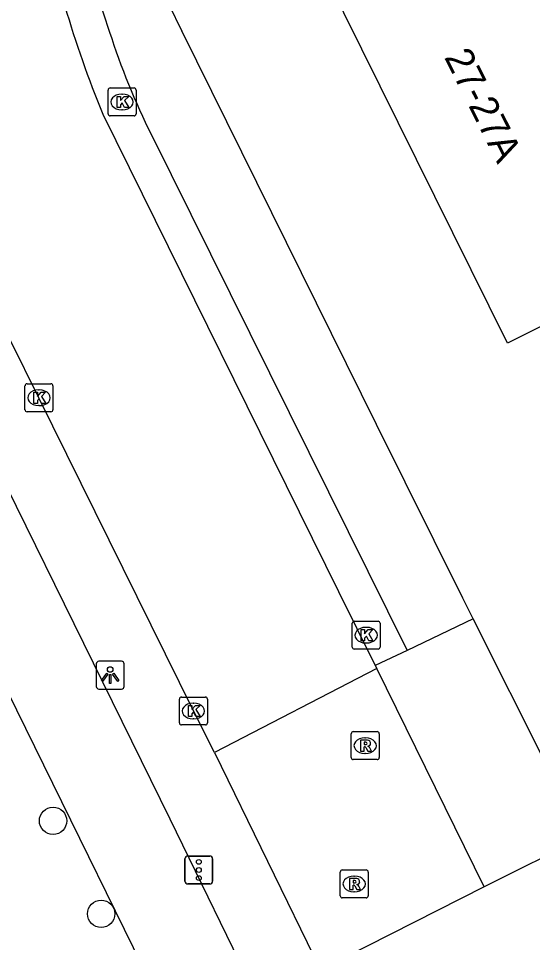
# Model space of a CAD drawing. Extents: x 157692 to 159670, y 381454 to 383289.
# Drawn here: x 158018.97 to 158037.36, y 381561.46 to 381594.48 of the extents above; entities that cross this region are included whole.
import ezdxf

# ---------------------------------------------------------------- set-up
doc = ezdxf.new("R2010")
doc.units = 0
for name, color, linetype in [('IMGEO_Boom', 7, 'Continuous'), ('IMGEO_Fietspad_gesloten', 7, 'Continuous'), ('IMGEO_Groenvoorziening', 7, 'Continuous'), ('IMGEO_Kolk', 7, 'Continuous'), ('IMGEO_Lichtpunt', 7, 'Continuous'), ('IMGEO_Pand', 7, 'Continuous'), ('IMGEO_Pand_nummerreeks', 7, 'Continuous'), ('IMGEO_Rijbaan_lokaal_gesloten', 7, 'Continuous'), ('IMGEO_Rioolput', 7, 'Continuous'), ('IMGEO_Verkeersregelinstallatiepaal', 7, 'Continuous'), ('IMGEO_Voetpad_open', 7, 'Continuous')]:
    doc.layers.add(name, color=color, linetype=linetype)

msp = doc.modelspace()

# ---------------------------------------------------------------- linework, layer by layer
at = {"layer": 'IMGEO_Boom'}
for centre in [(158020.207, 381565.809), (158021.932, 381562.486)]:
    msp.add_circle(centre, 0.489, dxfattribs=at)
at = {"layer": 'IMGEO_Fietspad_gesloten'}
msp.add_lwpolyline([(158039.17, 381565.209), (158035.637, 381563.445)], dxfattribs=at)
at = {"layer": 'IMGEO_Groenvoorziening'}
msp.add_lwpolyline([(158010.552, 381586.734), (158023.394, 381560.624)], dxfattribs=at)
at = {"layer": 'IMGEO_Kolk'}
for p, q in [((158022.177, 381591.074), (158022.177, 381591.926)), ((158022.252, 381592), (158023.104, 381592)), ((158022.665, 381591.78), (158022.69, 381591.78)), ((158023.178, 381591.926), (158023.178, 381591.074)), ((158022.688, 381591.22), (158022.663, 381591.22)), ((158023.104, 381591), (158022.252, 381591)), ((158019.204, 381580.501), (158019.204, 381581.353)), ((158019.279, 381581.427), (158020.131, 381581.427)), ((158019.692, 381581.207), (158019.717, 381581.207)), ((158020.205, 381581.353), (158020.205, 381580.501)), ((158019.715, 381580.647), (158019.69, 381580.647)), ((158020.131, 381580.427), (158019.279, 381580.427)), ((158030.984, 381572.943), (158031.836, 381572.943)), ((158030.909, 381572.017), (158030.909, 381572.869)), ((158031.397, 381572.723), (158031.422, 381572.723)), ((158031.91, 381572.869), (158031.91, 381572.017)), ((158031.42, 381572.163), (158031.395, 381572.163)), ((158031.836, 381571.943), (158030.984, 381571.943)), ((158024.729, 381569.307), (158024.729, 381570.159)), ((158024.804, 381570.233), (158025.656, 381570.233)), ((158025.217, 381570.013), (158025.242, 381570.013)), ((158025.73, 381570.159), (158025.73, 381569.307)), ((158025.24, 381569.453), (158025.215, 381569.453)), ((158025.656, 381569.233), (158024.804, 381569.233))]:
    msp.add_line(p, q, dxfattribs=at)
for points in [[(158022.177, 381591.074), (158022.177, 381591.926)], [(158022.252, 381592), (158023.104, 381592)], [(158023.178, 381591.926), (158023.178, 381591.074)], [(158022.498, 381591.7), (158022.621, 381591.7), (158022.621, 381591.549), (158022.751, 381591.7), (158022.915, 381591.7), (158022.769, 381591.549), (158022.922, 381591.3), (158022.77, 381591.3), (158022.685, 381591.464), (158022.621, 381591.397), (158022.621, 381591.3), (158022.498, 381591.3), (158022.498, 381591.7)], [(158023.104, 381591), (158022.252, 381591)], [(158019.204, 381580.501), (158019.204, 381581.353)], [(158019.279, 381581.427), (158020.131, 381581.427)], [(158020.205, 381581.353), (158020.205, 381580.501)], [(158019.525, 381581.127), (158019.648, 381581.127), (158019.648, 381580.976), (158019.778, 381581.127), (158019.942, 381581.127), (158019.796, 381580.976), (158019.949, 381580.727), (158019.797, 381580.727), (158019.712, 381580.891), (158019.648, 381580.824), (158019.648, 381580.727), (158019.525, 381580.727), (158019.525, 381581.127)], [(158020.131, 381580.427), (158019.279, 381580.427)], [(158030.984, 381572.943), (158031.836, 381572.943)], [(158030.909, 381572.017), (158030.909, 381572.869)], [(158031.23, 381572.643), (158031.353, 381572.643), (158031.353, 381572.492), (158031.483, 381572.643), (158031.647, 381572.643), (158031.501, 381572.492), (158031.654, 381572.243), (158031.502, 381572.243), (158031.417, 381572.407), (158031.353, 381572.34), (158031.353, 381572.243), (158031.23, 381572.243), (158031.23, 381572.643)], [(158031.91, 381572.869), (158031.91, 381572.017)], [(158031.836, 381571.943), (158030.984, 381571.943)], [(158024.729, 381569.307), (158024.729, 381570.159)], [(158024.804, 381570.233), (158025.656, 381570.233)], [(158025.73, 381570.159), (158025.73, 381569.307)], [(158025.05, 381569.933), (158025.173, 381569.933), (158025.173, 381569.782), (158025.303, 381569.933), (158025.467, 381569.933), (158025.321, 381569.782), (158025.474, 381569.533), (158025.322, 381569.533), (158025.237, 381569.697), (158025.173, 381569.63), (158025.173, 381569.533), (158025.05, 381569.533), (158025.05, 381569.933)], [(158025.656, 381569.233), (158024.804, 381569.233)]]:
    msp.add_lwpolyline(points, dxfattribs=at)
for centre, start, end in [((158022.254, 381591.924), 91.552, 178.448), ((158022.254, 381591.924), 91.552, 178.448), ((158023.102, 381591.924), 1.552, 88.448), ((158023.102, 381591.924), 1.552, 88.448), ((158022.254, 381591.076), 181.552, 268.448), ((158022.254, 381591.076), 181.552, 268.448), ((158023.102, 381591.076), 271.552, 358.448), ((158023.102, 381591.076), 271.552, 358.448), ((158019.281, 381581.351), 91.552, 178.448), ((158019.281, 381581.351), 91.552, 178.448), ((158020.129, 381581.351), 1.552, 88.448), ((158020.129, 381581.351), 1.552, 88.448), ((158019.281, 381580.503), 181.552, 268.448), ((158019.281, 381580.503), 181.552, 268.448), ((158020.129, 381580.503), 271.552, 358.448), ((158020.129, 381580.503), 271.552, 358.448), ((158030.986, 381572.867), 91.552, 178.448), ((158030.986, 381572.867), 91.552, 178.448), ((158031.834, 381572.867), 1.552, 88.448), ((158031.834, 381572.867), 1.552, 88.448), ((158030.986, 381572.019), 181.552, 268.448), ((158030.986, 381572.019), 181.552, 268.448), ((158031.834, 381572.019), 271.552, 358.448), ((158031.834, 381572.019), 271.552, 358.448), ((158024.806, 381570.157), 91.552, 178.448), ((158024.806, 381570.157), 91.552, 178.448), ((158025.654, 381570.157), 1.552, 88.448), ((158025.654, 381570.157), 1.552, 88.448), ((158024.806, 381569.309), 181.552, 268.448), ((158024.806, 381569.309), 181.552, 268.448), ((158025.654, 381569.309), 271.552, 358.448), ((158025.654, 381569.309), 271.552, 358.448)]:
    msp.add_arc(centre, 0.0765, start, end, dxfattribs=at)
for centre, major_axis, ratio, start_param, end_param in [((158022.664, 381591.5), (-0.387, 0.002), 0.722429, 4.712389, 7.853982), ((158022.689, 381591.5), (-0.39, 0.002), 0.717154, 1.570796, 4.712389), ((158019.691, 381580.927), (-0.387, 0.002), 0.722429, 4.712389, 7.853982), ((158019.716, 381580.927), (-0.39, 0.002), 0.717154, 1.570796, 4.712389), ((158031.396, 381572.443), (-0.387, 0.002), 0.722429, 4.712389, 7.853982), ((158031.421, 381572.443), (-0.39, 0.002), 0.717154, 1.570796, 4.712389), ((158025.216, 381569.733), (-0.387, 0.002), 0.722429, 4.712389, 7.853982), ((158025.241, 381569.733), (-0.39, 0.002), 0.717154, 1.570796, 4.712389)]:
    msp.add_ellipse(centre, major_axis=major_axis, ratio=ratio, start_param=start_param, end_param=end_param, dxfattribs=at)
at = {"layer": 'IMGEO_Lichtpunt'}
for p, q in [((158021.754, 381571.417), (158021.754, 381570.61)), ((158021.754, 381571.417), (158021.754, 381570.61)), ((158022.656, 381571.512), (158021.848, 381571.512)), ((158022.656, 381571.512), (158021.848, 381571.512)), ((158022.75, 381570.61), (158022.75, 381571.417)), ((158022.75, 381570.61), (158022.75, 381571.417)), ((158021.848, 381570.516), (158022.656, 381570.516)), ((158021.848, 381570.516), (158022.656, 381570.516))]:
    msp.add_line(p, q, dxfattribs=at)
for points in [[(158022.128, 381571.081), (158022.167, 381571.053), (158021.979, 381570.791), (158021.941, 381570.818), (158022.128, 381571.081)], [(158022.23, 381571.033), (158022.277, 381571.033), (158022.277, 381570.711), (158022.23, 381570.711), (158022.23, 381571.033)], [(158022.34, 381571.053), (158022.378, 381571.08), (158022.565, 381570.818), (158022.526, 381570.79), (158022.34, 381571.053)]]:
    msp.add_lwpolyline(points, dxfattribs=at)
msp.add_circle((158022.253, 381571.215), 0.0994, dxfattribs=at)
for centre, start, end in [((158021.848, 381571.417), 90, 180), ((158021.848, 381571.417), 90, 180), ((158022.656, 381571.417), 0, 90), ((158022.656, 381571.417), 0, 90), ((158021.848, 381570.61), 180, 270), ((158021.848, 381570.61), 180, 270), ((158022.656, 381570.61), 270, 0), ((158022.656, 381570.61), 270, 360)]:
    msp.add_arc(centre, 0.0946, start, end, dxfattribs=at)
at = {"layer": 'IMGEO_Pand'}
msp.add_lwpolyline([(158064.672, 381611.766), (158072.18, 381596.56), (158069.93, 381589.9), (158051.49, 381580.76), (158047.667, 381588.475), (158036.468, 381582.877), (158029.955, 381596.02), (158031.319, 381597.702), (158028.607, 381603.083), (158026.871, 381602.244), (158026.64, 381602.71), (158028.252, 381603.508)], dxfattribs=at)
at = {"layer": 'IMGEO_Rijbaan_lokaal_gesloten'}
for points in [[(158021.989, 381591.063), (158030.425, 381574.007), (158031.735, 381571.355)], [(158025.98, 381568.248), (158025.23, 381569.733), (158019.705, 381580.927), (158017.655, 381585.024)], [(158031.735, 381571.355), (158031.795, 381571.252)], [(158031.795, 381571.252), (158025.98, 381568.248)], [(158035.637, 381563.445), (158031.795, 381571.252)], [(158025.98, 381568.248), (158029.771, 381560.479)], [(158035.637, 381563.445), (158029.771, 381560.479)]]:
    msp.add_lwpolyline(points, dxfattribs=at)
msp.add_arc((158058.796, 381606.188), 39.793, 196.4431, 202.3392, dxfattribs=at)
at = {"layer": 'IMGEO_Rioolput'}
for p, q in [((158030.949, 381568.995), (158031.801, 381568.995)), ((158030.874, 381568.069), (158030.874, 381568.921)), ((158031.362, 381568.775), (158031.387, 381568.775)), ((158031.875, 381568.921), (158031.875, 381568.069)), ((158031.801, 381567.995), (158030.949, 381567.995)), ((158031.385, 381568.215), (158031.36, 381568.215)), ((158030.556, 381564.052), (158031.408, 381564.052)), ((158030.481, 381563.126), (158030.481, 381563.978)), ((158030.969, 381563.832), (158030.994, 381563.832)), ((158031.482, 381563.978), (158031.482, 381563.126)), ((158031.408, 381563.052), (158030.556, 381563.052)), ((158030.992, 381563.272), (158030.967, 381563.272))]:
    msp.add_line(p, q, dxfattribs=at)
for points in [[(158030.949, 381568.995), (158031.801, 381568.995)], [(158030.874, 381568.069), (158030.874, 381568.921)], [(158031.463, 381568.693), (158031.211, 381568.695), (158031.211, 381568.295)], [(158031.875, 381568.921), (158031.875, 381568.069)], [(158031.211, 381568.295), (158031.335, 381568.295), (158031.335, 381568.457), (158031.346, 381568.457)], [(158031.389, 381568.614), (158031.335, 381568.614), (158031.335, 381568.533)], [(158031.335, 381568.533), (158031.387, 381568.533)], [(158031.393, 381568.428), (158031.464, 381568.295), (158031.604, 381568.295), (158031.539, 381568.421)], [(158031.801, 381567.995), (158030.949, 381567.995)], [(158030.556, 381564.052), (158031.408, 381564.052)], [(158030.481, 381563.126), (158030.481, 381563.978)], [(158031.07, 381563.75), (158030.818, 381563.752), (158030.818, 381563.352)], [(158031.482, 381563.978), (158031.482, 381563.126)], [(158030.818, 381563.352), (158030.942, 381563.352), (158030.942, 381563.514), (158030.953, 381563.514)], [(158030.996, 381563.671), (158030.942, 381563.671), (158030.942, 381563.59)], [(158030.942, 381563.59), (158030.994, 381563.59)], [(158031, 381563.485), (158031.071, 381563.352), (158031.211, 381563.352), (158031.146, 381563.478)], [(158031.408, 381563.052), (158030.556, 381563.052)]]:
    msp.add_lwpolyline(points, dxfattribs=at)
for centre, radius, start, end in [((158030.951, 381568.919), 0.0765, 91.552, 178.448), ((158030.951, 381568.919), 0.0765, 91.552, 178.448), ((158031.799, 381568.919), 0.0765, 1.552, 88.448), ((158031.799, 381568.919), 0.0765, 1.552, 88.448), ((158031.462, 381568.583), 0.109, 350.3612, 89.416), ((158031.345, 381568.404), 0.0533, 26.0293, 88.6989), ((158031.371, 381568.722), 0.19, 274.7715, 282.9687), ((158031.395, 381568.518), 0.0964, 77.0061, 93.1865), ((158031.409, 381568.575), 0.0378, 276.6634, 79.6772), ((158031.46, 381568.583), 0.112, 277.5842, 350.9817), ((158031.444, 381568.368), 0.108, 29.5134, 73.7905), ((158030.951, 381568.071), 0.0765, 181.552, 268.448), ((158030.951, 381568.071), 0.0765, 181.552, 268.448), ((158031.799, 381568.071), 0.0765, 271.552, 358.448), ((158031.799, 381568.071), 0.0765, 271.552, 358.448), ((158030.558, 381563.976), 0.0765, 91.552, 178.448), ((158030.558, 381563.976), 0.0765, 91.552, 178.448), ((158031.406, 381563.976), 0.0765, 1.552, 88.448), ((158031.406, 381563.976), 0.0765, 1.552, 88.448), ((158031.069, 381563.64), 0.109, 350.3612, 89.416), ((158030.952, 381563.461), 0.0533, 26.0293, 88.6989), ((158030.978, 381563.779), 0.19, 274.7715, 282.9687), ((158031.002, 381563.575), 0.0964, 77.0061, 93.1865), ((158031.016, 381563.632), 0.0378, 276.6634, 79.6772), ((158031.067, 381563.64), 0.112, 277.5842, 350.9817), ((158031.051, 381563.425), 0.108, 29.5134, 73.7905), ((158030.558, 381563.128), 0.0765, 181.552, 268.448), ((158030.558, 381563.128), 0.0765, 181.552, 268.448), ((158031.406, 381563.128), 0.0765, 271.552, 358.448), ((158031.406, 381563.128), 0.0765, 271.552, 358.448)]:
    msp.add_arc(centre, radius, start, end, dxfattribs=at)
for centre, major_axis, ratio, start_param, end_param in [((158031.361, 381568.495), (-0.387, 0.002), 0.722429, 4.712389, 7.853982), ((158031.386, 381568.495), (-0.39, 0.002), 0.717154, 1.570796, 4.712389), ((158030.968, 381563.552), (-0.387, 0.002), 0.722429, 4.712389, 7.853982), ((158030.993, 381563.552), (-0.39, 0.002), 0.717154, 1.570796, 4.712389)]:
    msp.add_ellipse(centre, major_axis=major_axis, ratio=ratio, start_param=start_param, end_param=end_param, dxfattribs=at)
at = {"layer": 'IMGEO_Verkeersregelinstallatiepaal'}
for p, q in [((158024.928, 381563.65), (158024.928, 381564.45)), ((158024.928, 381564.45), (158024.928, 381563.65)), ((158025.028, 381564.55), (158025.818, 381564.55)), ((158025.818, 381564.55), (158025.028, 381564.55)), ((158025.918, 381564.45), (158025.918, 381563.65)), ((158025.918, 381563.65), (158025.918, 381564.45)), ((158025.818, 381563.55), (158025.028, 381563.55)), ((158025.028, 381563.55), (158025.818, 381563.55))]:
    msp.add_line(p, q, dxfattribs=at)
for centre in [(158025.423, 381564.34), (158025.423, 381564.05), (158025.423, 381563.76)]:
    msp.add_circle(centre, 0.085, dxfattribs=at)
for centre, start, end in [((158025.028, 381564.45), 90, 180), ((158025.028, 381564.45), 90, 180), ((158025.818, 381564.45), 0, 90), ((158025.818, 381564.45), 360, 90), ((158025.028, 381563.65), 180, 270), ((158025.028, 381563.65), 180, 270), ((158025.818, 381563.65), 270, 0), ((158025.818, 381563.65), 270, 0)]:
    msp.add_arc(centre, 0.1, start, end, dxfattribs=at)
at = {"layer": 'IMGEO_Voetpad_open'}
for points in [[(158021.777, 381595.384), (158022.229, 381593.999)], [(158035.242, 381573.028), (158034.874, 381573.76), (158031.774, 381579.967), (158024.817, 381594.042)], [(158023.726, 381590.325), (158032.874, 381571.898)], [(158027.557, 381559.385), (158024.393, 381565.87), (158015.453, 381584.017)], [(158035.242, 381573.028), (158032.874, 381571.898)], [(158037.877, 381567.782), (158035.242, 381573.028)], [(158032.874, 381571.898), (158031.735, 381571.355)]]:
    msp.add_lwpolyline(points, dxfattribs=at)
for centre, radius, start, end in [((158047.696, 381605.866), 25.754, 202.0321, 207.3299), ((158047.797, 381602.275), 26.874, 197.9358, 206.4018)]:
    msp.add_arc(centre, radius, start, end, dxfattribs=at)

# ---------------------------------------------------------------- texts
at = {"layer": 'IMGEO_Pand_nummerreeks'}
msp.add_text('27-27A', height=1, rotation=296.6354, dxfattribs=at).set_placement((158034.187, 381593.103))

doc.saveas('drawing.dxf')
